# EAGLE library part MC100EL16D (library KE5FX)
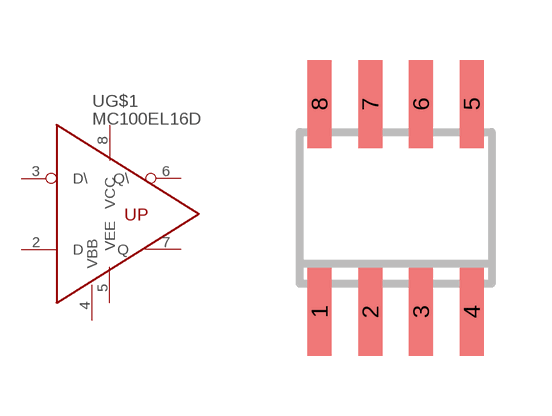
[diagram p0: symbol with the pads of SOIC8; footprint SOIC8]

Designator prefix U; gates G$1=ECL_BUFFER P=VCC_VEE

## MC100EL16D  [SOIC8]
2  G$1:D  in
3  G$1:D\  in
4  G$1:VBB  in
5  P:VEE  pwr
6  G$1:Q\  out
7  G$1:Q  out
8  P:VCC  pwr

## Footprint SOIC8 (pad centres in mm)
smd 0.6 x 2.2: 1 1.27,-0.06; 2 2.54,-0.06; 3 3.81,-0.06; 4 5.08,-0.06; 5 5.08,5.14; 6 3.81,5.14; 7 2.54,5.14; 8 1.27,5.14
